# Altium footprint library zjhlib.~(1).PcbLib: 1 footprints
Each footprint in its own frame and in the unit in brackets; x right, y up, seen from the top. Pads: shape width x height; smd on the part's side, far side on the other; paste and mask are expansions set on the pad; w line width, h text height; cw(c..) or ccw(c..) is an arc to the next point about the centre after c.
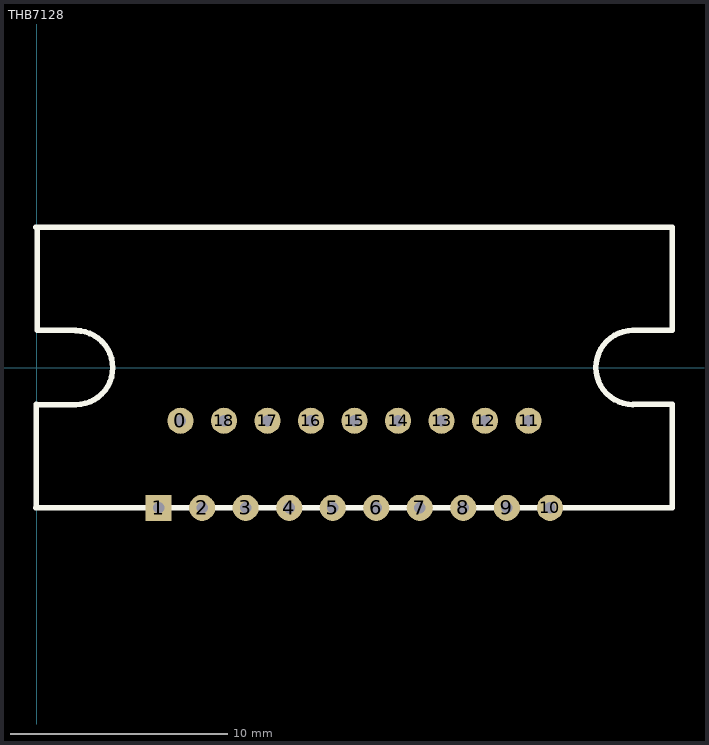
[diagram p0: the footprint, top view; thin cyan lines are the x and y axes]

## THB7128 [mm]
pads (19):
  round 1.2 hole 0.52: 0(6.61,-2.44) 2(7.61,-6.44) 3(9.61,-6.44) 4(11.61,-6.44) 5(13.61,-6.44) 6(15.61,-6.44) 7(17.61,-6.44) 8(19.61,-6.44) 9(21.61,-6.44) 10(23.593,-6.44) 11(22.61,-2.44) 12(20.61,-2.44) 13(18.61,-2.44) 14(16.61,-2.44) 15(14.61,-2.44) 16(12.61,-2.44) 17(10.61,-2.44) 18(8.61,-2.44)
  rect 1.2x1.2 hole 0.52: 1(5.61,-6.44)
Top Overlay:
  lines w0.254: -0.035,-6.441 29.21,-6.441 ; -0.035,6.459 29.21,6.459 ; -0.013,-6.419 -0.013,-1.69 ; -0.003,-1.7 1.802,-1.7 ccw(c1.801,0) 1.802,1.7 ; 0.031,6.393 0.031,1.709 1.792,1.709 ; 27.404,-1.696 cw(c27.409,0.009) 27.405,1.713 29.2,1.713 ; 27.409,-1.691 29.205,-1.691 29.205,-6.436 ; 29.205,1.718 29.205,6.454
